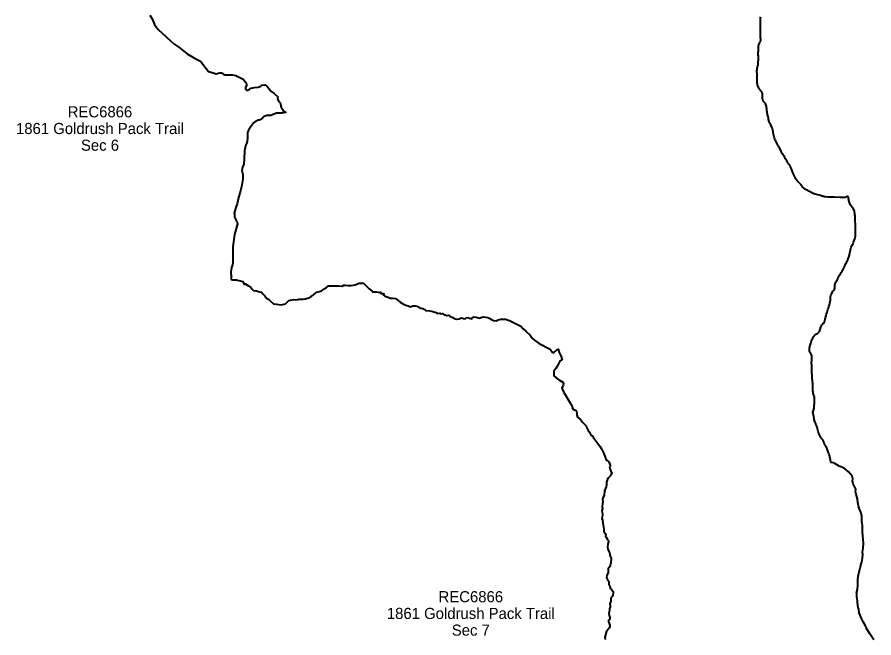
# Model space of a CAD drawing. Extents: x 322505 to 642419, y 5806860 to 5919753.
# Drawn here: x 603068 to 610765, y 5865060 to 5870637 of the extents above; entities that cross this region are included whole.
import ezdxf
from ezdxf.enums import TextEntityAlignment as Align

# ---------------------------------------------------------------- set-up
doc = ezdxf.new("R2010")
doc.units = 0
doc.header["$LTSCALE"] = 140
doc.layers.add('4', color=7, linetype='Continuous', lineweight=40)
doc.layers.add('5', color=7, linetype='Continuous', lineweight=40)

msp = doc.modelspace()

# ---------------------------------------------------------------- linework, layer by layer
at = {"layer": '4'}
for points in [[(604262, 5870655), (604282, 5870623), (604303, 5870571), (604308, 5870561), (604336, 5870526), (604408, 5870459), (604475, 5870399), (604522, 5870368), (604597, 5870309), (604663, 5870268), (604715, 5870243), (604788, 5870148), (604822, 5870141), (604858, 5870128), (604868, 5870130), (604876, 5870135), (604889, 5870138), (604904, 5870138), (604914, 5870132), (604926, 5870121), (604934, 5870119), (605004, 5870119), (605033, 5870114), (605099, 5870079), (605125, 5870047), (605130, 5870028), (605129, 5870019), (605121, 5870005), (605120, 5869989), (605128, 5869981), (605140, 5869981), (605152, 5869986), (605171, 5869998), (605185, 5870003), (605200, 5870005), (605235, 5870007), (605258, 5870017), (605268, 5870025), (605297, 5870030), (605312, 5870016)], [(605312, 5870016), (605317, 5870011), (605332, 5869993), (605347, 5869973), (605377, 5869951), (605413, 5869918), (605409, 5869912), (605409, 5869905), (605411, 5869896), (605418, 5869882), (605428, 5869871), (605436, 5869858), (605437, 5869837), (605440, 5869830), (605451, 5869811), (605464, 5869794), (605482, 5869781), (605480, 5869781), (605475, 5869781), (605471, 5869781), (605466, 5869780), (605460, 5869779), (605453, 5869777), (605445, 5869776), (605437, 5869775), (605433, 5869775), (605429, 5869775), (605425, 5869775), (605422, 5869775), (605419, 5869775), (605417, 5869775), (605413, 5869775), (605409, 5869775), (605405, 5869774), (605400, 5869774), (605396, 5869773), (605392, 5869772), (605388, 5869771), (605385, 5869769), (605383, 5869769), (605379, 5869767), (605375, 5869765), (605370, 5869763), (605364, 5869760), (605359, 5869758), (605355, 5869756), (605350, 5869755), (605346, 5869755), (605341, 5869754), (605336, 5869754), (605331, 5869754), (605327, 5869754), (605322, 5869754), (605318, 5869754), (605315, 5869754), (605313, 5869754), (605298, 5869748), (605281, 5869741), (605279, 5869739), (605278, 5869738), (605275, 5869735), (605273, 5869732), (605270, 5869728), (605266, 5869726), (605265, 5869724), (605263, 5869722), (605261, 5869721), (605260, 5869719), (605259, 5869718), (605257, 5869717), (605254, 5869716), (605251, 5869715), (605249, 5869714), (605248, 5869714), (605244, 5869713), (605237, 5869711), (605229, 5869708), (605223, 5869705), (605217, 5869702), (605212, 5869699)], [(605212, 5869699), (605207, 5869696), (605201, 5869692), (605195, 5869688), (605189, 5869684), (605185, 5869680), (605182, 5869677), (605179, 5869673), (605176, 5869669), (605173, 5869664), (605170, 5869659), (605164, 5869649), (605158, 5869640), (605152, 5869631), (605147, 5869622), (605143, 5869613), (605141, 5869607), (605139, 5869601), (605139, 5869594), (605138, 5869587), (605138, 5869580), (605138, 5869573), (605139, 5869568), (605139, 5869566), (605139, 5869558), (605139, 5869549), (605138, 5869540), (605136, 5869530), (605134, 5869520), (605131, 5869511), (605128, 5869503), (605125, 5869497), (605122, 5869490), (605120, 5869481), (605117, 5869471), (605116, 5869460), (605113, 5869451), (605112, 5869439), (605111, 5869427), (605110, 5869415), (605110, 5869402), (605109, 5869390), (605109, 5869378), (605109, 5869365), (605109, 5869363), (605104, 5869316), (605093, 5869289), (605087, 5869256), (605089, 5869248), (605095, 5869224), (605097, 5869208), (605095, 5869188), (605095, 5869186), (605087, 5869127), (605072, 5869064), (605058, 5869016), (605044, 5868960), (605034, 5868928), (605018, 5868875), (605020, 5868867), (605022, 5868845), (605025, 5868833), (605026, 5868831), (605034, 5868816), (605043, 5868804), (605047, 5868779), (605022, 5868685), (605008, 5868599), (605005, 5868572), (605007, 5868485), (605007, 5868434), (605002, 5868411), (604995, 5868389), (604987, 5868347), (604992, 5868308), (604993, 5868306), (604992, 5868296), (604989, 5868279)], [(604989, 5868279), (605003, 5868278.5), (605039.1, 5868276), (605049, 5868274), (605084.4, 5868265.8), (605096.6, 5868262.2), (605107.1, 5868235.6), (605118.5, 5868239.9), (605147.2, 5868223.6), (605167.9, 5868209.1), (605180.6, 5868194.1), (605192.8, 5868180.3), (605219, 5868179), (605245.7, 5868169.6), (605263.3, 5868165.1), (605280.2, 5868147.7), (605293.5, 5868133.7), (605309.1, 5868112.6), (605325.4, 5868104.6), (605342.7, 5868088), (605371.4, 5868061), (605399.5, 5868058.7), (605439.4, 5868054), (605480.2, 5868062.2), (605493.4, 5868076.3), (605509.5, 5868090), (605525.2, 5868094.7), (605550.5, 5868101.5), (605568, 5868098.1), (605589, 5868099.4), (605600.7, 5868104), (605617.8, 5868104.4), (605638.1, 5868102.5), (605658.3, 5868105.1), (605688.4, 5868114.5), (605709.2, 5868127.3), (605731.3, 5868141.2), (605752.4, 5868160.4), (605758.9, 5868166.7), (605799.3, 5868176.7), (605832.9, 5868198.3), (605844.7, 5868205.3), (605864.4, 5868223.8), (605928, 5868221.8), (605959.7, 5868223), (605990, 5868219.3), (606003.8, 5868229.1), (606019.9, 5868229.7), (606041.4, 5868225.1), (606070, 5868225.4), (606104.5, 5868232), (606138.5, 5868248.6), (606178.7, 5868248.5), (606207.2, 5868219.7), (606231.6, 5868195.8), (606259.4, 5868174.2), (606260.9, 5868170.3), (606295.7, 5868170.7), (606312.9, 5868167.1), (606323.3, 5868163.2), (606328.7, 5868166.9), (606332.9, 5868166.9), (606336.5, 5868156.1), (606341.8, 5868153.7), (606344.6, 5868152.7), (606352.7, 5868155.1), (606361.2, 5868153.1), (606363.5, 5868149)], [(606363.5, 5868149), (606362.7, 5868145.8), (606360.7, 5868144.9), (606360, 5868138.6), (606367.4, 5868133.5), (606371.9, 5868132.8), (606374.8, 5868129.3), (606389.7, 5868124.2), (606402.7, 5868121.2), (606419.2, 5868113.1), (606444.6, 5868111.2), (606466.7, 5868108.8), (606488.5, 5868094.1), (606510.5, 5868077.9), (606539.3, 5868059.1), (606559.2, 5868048.6), (606582.7, 5868042.1), (606602.9, 5868035.9), (606624.7, 5868042.7), (606647.3, 5868044.8), (606662.6, 5868041), (606696, 5868022.8), (606714.4, 5868019), (606730.3, 5868010.5), (606739, 5868001.6), (606777.1, 5867998.1), (606793.1, 5867996.4), (606821.5, 5867986.9), (606834, 5867984.3), (606846.5, 5867974.7), (606867.1, 5867977.5), (606874.7, 5867973), (606890.7, 5867974.7), (606910.1, 5867962.2), (606926.1, 5867956.8), (606944.9, 5867959), (606958.3, 5867947.1), (606984.1, 5867939.8), (606995.3, 5867928.7), (607016.9, 5867925), (607040.1, 5867928.2), (607058.5, 5867935.4), (607077.5, 5867930.9), (607092.9, 5867926.6), (607103, 5867936), (607116.8, 5867939.6), (607133, 5867931.8), (607153.9, 5867927.6), (607160.8, 5867938.8), (607170.8, 5867944.6), (607192, 5867941.5), (607221.1, 5867932.8), (607244.5, 5867941.8), (607259.8, 5867944.4), (607295.8, 5867940.2), (607313.7, 5867929.7), (607330.2, 5867921.5), (607347.2, 5867911.9), (607373, 5867909), (607390.7, 5867916.8), (607413.3, 5867924.3), (607430.5, 5867924.1), (607454.4, 5867923.3), (607473.4, 5867917.6), (607498.6, 5867909.8), (607594.3, 5867861.4), (607614.1, 5867838.3), (607639.3, 5867817.3), (607677.9, 5867778.5), (607696.4, 5867753.8), (607715, 5867735.8), (607738.7, 5867720.3), (607759, 5867705.1)], [(607759, 5867705.1), (607858.1, 5867654.8), (607878, 5867625), (607883.6, 5867623.1), (607890.8, 5867623.4), (607905.3, 5867635.1), (607920.1, 5867652.6), (607928.8, 5867654.2), (607938, 5867625.2), (607956, 5867587.9), (607965.6, 5867558.4), (607943.3, 5867544.9), (607932.2, 5867521.5), (607909.4, 5867480.9), (607890.3, 5867456.3), (607890.9, 5867414.5), (607924.9, 5867383.4), (607936.4, 5867379.3), (607970.2, 5867356.9), (607976.3, 5867343.3), (607972.5, 5867330.5), (607961.9, 5867302.4), (607969.4, 5867291.3), (607976, 5867270.3), (608011.8, 5867211.5), (608040.6, 5867166.1), (608052.7, 5867152), (608055.9, 5867128.6), (608063.6, 5867114.1), (608081, 5867105.1), (608089.6, 5867101.2), (608093.8, 5867093.6), (608096.5, 5867080), (608097.1, 5867063.5), (608103.5, 5867044.4), (608128.3, 5867022.2), (608146.5, 5866999.3), (608179.8, 5866964), (608183.9, 5866953.6), (608195.1, 5866929.5), (608209.8, 5866909.5), (608218.8, 5866889.3), (608226.2, 5866882.7), (608236.3, 5866876.1), (608243.2, 5866864.3), (608250.8, 5866853.1), (608286.8, 5866805.4), (608303.2, 5866781.4), (608319.4, 5866757.9), (608339.1, 5866718), (608361.5, 5866660.1), (608373, 5866653.8), (608383.1, 5866641), (608394.9, 5866612.6), (608395, 5866601), (608391.5, 5866595), (608391.8, 5866581.5), (608402.6, 5866558.8), (608409.8, 5866537.9), (608409.1, 5866532.1), (608395.2, 5866512.2), (608385.4, 5866500.3), (608375, 5866493.8), (608363.5, 5866458), (608363.4, 5866431.1), (608359.1, 5866418), (608346.1, 5866382), (608342.3, 5866338.2), (608333.2, 5866324.5), (608328, 5866307.2), (608329.5, 5866281.9), (608326.1, 5866268.5), (608324.8, 5866237.1), (608325.9, 5866222.3), (608322.2, 5866203.7), (608326.4, 5866168.8), (608327.9, 5866162.9)], [(608327.9, 5866162.9), (608323.9, 5866144.3), (608321.6, 5866131.7), (608325.9, 5866117.6), (608333.2, 5866073.9), (608335.2, 5866054.3), (608339.7, 5866038.4), (608337.9, 5866028.7), (608339, 5866014.7), (608354.2, 5865994.1), (608357.9, 5865985.4), (608353.7, 5865975.2), (608353.8, 5865970.9), (608360.2, 5865963.7), (608370.4, 5865950.4), (608377.7, 5865936.7), (608381, 5865925.9), (608375.1, 5865898.9), (608372.7, 5865876.2), (608379.1, 5865847.2), (608390.4, 5865828.7), (608391.8, 5865812.3), (608393.3, 5865801.6), (608400.9, 5865783.7), (608405.1, 5865774.8), (608406, 5865769.7), (608403.5, 5865737.4), (608399.1, 5865723.5), (608393.2, 5865701.9), (608378.6, 5865680.2), (608378.4, 5865647.6), (608365.5, 5865619.2), (608363.6, 5865602.5), (608366.2, 5865593.1), (608372.5, 5865586.3), (608373.6, 5865577.8), (608383, 5865565.4), (608382.7, 5865548.9), (608385, 5865541.7), (608390.6, 5865532.4), (608392.8, 5865522), (608398.1, 5865501.8), (608409.2, 5865495.8), (608423.3, 5865477.9), (608422.6, 5865464.3), (608420.4, 5865443.1), (608415.8, 5865434.6), (608405.9, 5865422.7), (608402.3, 5865409.1), (608401, 5865391.2), (608395.9, 5865375.6), (608394.3, 5865365.4), (608395.3, 5865344.6), (608396.6, 5865331.3), (608392.1, 5865329), (608390.9, 5865325.2), (608390.8, 5865311.5), (608387.3, 5865293.6), (608384.3, 5865277.8), (608391.4, 5865252.9), (608392.8, 5865242.9), (608391.7, 5865229.1), (608381.4, 5865218.4), (608382.3, 5865204.9), (608388.6, 5865189.3), (608392.4, 5865175.2), (608392.4, 5865159.8), (608385.2, 5865144.2), (608374.4, 5865133.5), (608362.5, 5865120.7), (608355.6, 5865086.6), (608349, 5865066.5), (608351.1, 5865044.6)]]:
    msp.add_lwpolyline(points, dxfattribs=at)
at = {"layer": '5'}
for points in [[(609746, 5870417), (609748, 5870422), (609749, 5870428), (609749, 5870435), (609749, 5870441), (609748, 5870448), (609748, 5870453), (609747, 5870459), (609747, 5870464), (609747, 5870470), (609747, 5870478), (609747, 5870486), (609747, 5870495), (609747, 5870504), (609747, 5870511), (609747, 5870518), (609747, 5870525), (609746, 5870534), (609746, 5870543), (609746, 5870551), (609746, 5870560), (609746, 5870568), (609746, 5870575), (609746, 5870583), (609746, 5870592), (609747, 5870602), (609747, 5870613), (609748, 5870623), (609748, 5870632), (609749, 5870639)], [(609851, 5869643), (609847, 5869652), (609843, 5869661), (609839, 5869670), (609835, 5869678), (609832, 5869684), (609829, 5869691), (609826, 5869699), (609823, 5869709), (609820, 5869719), (609818, 5869730), (609815, 5869741), (609813, 5869750), (609811, 5869760), (609810, 5869769), (609808, 5869779), (609807, 5869789), (609805, 5869797), (609803, 5869815), (609803, 5869817), (609802, 5869825), (609800, 5869834), (609798, 5869843), (609796, 5869851), (609792, 5869860), (609790, 5869864), (609782, 5869871), (609772, 5869883), (609766, 5869907), (609765, 5869939), (609764, 5869951), (609756, 5869970), (609754, 5869971), (609751, 5869975), (609746, 5869980), (609741, 5869987), (609739, 5869990), (609737, 5869992), (609736, 5869995), (609734, 5869997), (609733, 5870000), (609730, 5870005), (609728, 5870010), (609725, 5870015), (609723, 5870021), (609721, 5870025), (609720, 5870031), (609719, 5870038), (609718, 5870045), (609718, 5870054), (609718, 5870063), (609718, 5870073), (609718, 5870080), (609718, 5870087), (609718, 5870093), (609717, 5870100), (609717, 5870106), (609717, 5870112), (609717, 5870118), (609717, 5870124), (609716, 5870129), (609716, 5870135), (609715, 5870141), (609715, 5870148), (609715, 5870156), (609716, 5870164), (609717, 5870176), (609719, 5870185), (609721, 5870193), (609722, 5870197), (609723, 5870201), (609725, 5870209), (609726, 5870217), (609727, 5870226), (609727, 5870234), (609727, 5870242), (609728, 5870248), (609728, 5870254), (609728, 5870261), (609728, 5870269), (609728, 5870277), (609728, 5870287), (609727, 5870296), (609727, 5870303), (609727, 5870310), (609727, 5870316), (609727, 5870323), (609728, 5870332), (609728, 5870341), (609729, 5870351), (609730, 5870359), (609729, 5870366), (609729, 5870371), (609729, 5870376), (609730, 5870382), (609731, 5870389), (609734, 5870396), (609737, 5870403), (609740, 5870408), (609743, 5870413), (609746, 5870417)], [(610316, 5869025), (610308, 5869027), (610301, 5869029), (610296, 5869031), (610291, 5869033), (610286, 5869035), (610274, 5869038), (610262, 5869041), (610250, 5869045), (610238, 5869048), (610228, 5869050), (610224, 5869052), (610218, 5869054), (610212, 5869057), (610205, 5869061), (610198, 5869065), (610188, 5869070), (610180, 5869075), (610172, 5869079), (610166, 5869082), (610158, 5869086), (610152, 5869090), (610146, 5869093), (610139, 5869097), (610134, 5869101), (610130, 5869104), (610126, 5869108), (610123, 5869113), (610120, 5869119), (610116, 5869125), (610111, 5869132), (610105, 5869138), (610101, 5869143), (610096, 5869147), (610092, 5869151), (610088, 5869156), (610084, 5869159), (610081, 5869163), (610078, 5869167), (610077, 5869168), (610075, 5869170), (610073, 5869173), (610068, 5869180), (610062, 5869188), (610058, 5869197), (610052, 5869208), (610047, 5869221), (610043, 5869229), (610040, 5869236), (610038, 5869242), (610035, 5869249), (610032, 5869255), (610028, 5869265), (610024, 5869275), (610019, 5869285), (610015, 5869293), (610015, 5869294), (610011, 5869302), (610009, 5869306), (610006, 5869311), (610002, 5869316), (609997, 5869322), (609993, 5869329), (609985, 5869341), (609980, 5869349), (609979, 5869350), (609974, 5869358), (609969, 5869366), (609964, 5869375), (609958, 5869384), (609952, 5869393), (609946, 5869403), (609941, 5869411), (609937, 5869418), (609934, 5869424), (609931, 5869432), (609927, 5869442), (609922, 5869452), (609917, 5869463), (609912, 5869471), (609907, 5869478), (609903, 5869485), (609902, 5869487), (609899, 5869492), (609895, 5869499), (609891, 5869508), (609887, 5869516), (609884, 5869524), (609881, 5869531), (609879, 5869536), (609877, 5869542), (609874, 5869551), (609871, 5869561), (609868, 5869573), (609865, 5869586), (609862, 5869599), (609860, 5869609), (609860, 5869610), (609857, 5869621), (609854, 5869632), (609851, 5869643)], [(610567, 5868937), (610562, 5868942), (610558, 5868948), (610553, 5868955), (610549, 5868964), (610546, 5868973), (610543, 5868982), (610540, 5868990), (610539, 5868999), (610537, 5869007), (610537, 5869012), (610536.2, 5869017), (610536, 5869018), (610533.2, 5869022), (610529.2, 5869024.5), (610525.2, 5869025.5), (610521.6, 5869024), (610517, 5869021.5), (610511.6, 5869018), (610505.4, 5869017), (610462.1, 5869017.5), (610407.6, 5869018.5), (610355.6, 5869020), (610327, 5869022), (610322, 5869023), (610316, 5869025)], [(610294, 5867863), (610299, 5867872), (610305, 5867880), (610311, 5867887), (610315, 5867892), (610321, 5867900), (610324, 5867911), (610328, 5867923), (610332, 5867938), (610336, 5867955), (610341, 5867973), (610345, 5867987), (610349, 5868000), (610353, 5868011), (610357, 5868023), (610362, 5868037), (610367, 5868052), (610371, 5868067), (610374, 5868081), (610375, 5868093), (610376, 5868102), (610376, 5868113), (610377, 5868124), (610380, 5868136), (610384, 5868149), (610391, 5868163), (610398, 5868174), (610405, 5868183), (610411, 5868192), (610415, 5868202), (610416, 5868209), (610416, 5868216), (610416, 5868224), (610416, 5868231), (610417, 5868238), (610418, 5868244), (610421, 5868250), (610425, 5868257), (610429, 5868264), (610434, 5868272), (610438, 5868280), (610442, 5868287), (610445, 5868294), (610448, 5868300), (610451, 5868306), (610457, 5868318), (610465, 5868331), (610472, 5868343), (610480, 5868355), (610487, 5868367), (610492, 5868377), (610496, 5868387), (610501, 5868398), (610506, 5868410), (610513, 5868423), (610518, 5868434), (610523, 5868443), (610528, 5868450), (610532, 5868458), (610535, 5868466), (610538, 5868474), (610541, 5868482), (610543, 5868490), (610545, 5868498), (610547, 5868506), (610549, 5868520), (610551, 5868533), (610554, 5868546), (610557, 5868558), (610562, 5868570), (610565, 5868579), (610570, 5868587), (610574, 5868595), (610578, 5868604), (610583, 5868616), (610588, 5868632), (610593, 5868645), (610596, 5868657), (610599, 5868668), (610600, 5868679), (610601, 5868693), (610601, 5868708), (610601, 5868724), (610600, 5868740), (610599, 5868758), (610599, 5868771), (610599, 5868783), (610598, 5868795), (610598, 5868808), (610597, 5868823), (610597, 5868838), (610596, 5868851), (610595, 5868862), (610595, 5868873), (610592, 5868885), (610590, 5868894), (610586, 5868903), (610582, 5868912), (610577, 5868921), (610571, 5868930), (610567, 5868937)], [(610271, 5866898), (610268, 5866906), (610266, 5866915), (610262, 5866927), (610260, 5866937), (610258, 5866945), (610255, 5866953), (610253, 5866962), (610250, 5866968), (610248, 5866975), (610245, 5866981), (610243, 5866986), (610241, 5866991), (610238, 5866997), (610235, 5867004), (610233, 5867012), (610230, 5867021), (610228, 5867031), (610226, 5867042), (610225, 5867051), (610224, 5867058), (610223, 5867066), (610221, 5867074), (610220, 5867077), (610218, 5867083), (610217.1, 5867085.5), (610224, 5867104.5), (610227.8, 5867125.5), (610229.9, 5867146), (610230.6, 5867166.5), (610231.6, 5867187), (610231.9, 5867204.5), (610231, 5867226), (610226, 5867239), (610225.3, 5867241.5), (610223, 5867250), (610221, 5867260), (610219, 5867270), (610218, 5867280), (610218, 5867294), (610217, 5867308), (610217, 5867322), (610217, 5867336), (610216, 5867348), (610215, 5867361), (610214, 5867375), (610212, 5867389), (610211, 5867406), (610210, 5867424), (610209, 5867440), (610209, 5867453), (610208, 5867466), (610208, 5867477), (610208, 5867489), (610207, 5867501), (610207, 5867513), (610206, 5867526), (610206, 5867538), (610207, 5867550), (610208, 5867561), (610209, 5867572), (610209, 5867583), (610207, 5867596), (610203, 5867608), (610199, 5867615), (610196, 5867621), (610193, 5867626), (610190, 5867631), (610188, 5867637), (610187, 5867642), (610187, 5867649), (610187, 5867655), (610188, 5867661), (610188, 5867666), (610189, 5867673), (610190, 5867680), (610192, 5867686), (610192, 5867687), (610195, 5867696), (610198, 5867706), (610202, 5867718), (610205, 5867728), (610208, 5867737), (610212, 5867745), (610216, 5867754), (610220, 5867762), (610226, 5867770), (610232, 5867778), (610239, 5867784), (610246, 5867790), (610252, 5867793), (610258, 5867796), (610265, 5867800), (610271, 5867806), (610276, 5867813), (610281, 5867822), (610283, 5867831), (610285, 5867839), (610287, 5867847), (610289, 5867855), (610294, 5867863)], [(610765.2, 5865042), (610753.5, 5865061), (610747, 5865069.5), (610730.1, 5865096), (610696.2, 5865151), (610692.2, 5865162), (610692.2, 5865163.5), (610689.6, 5865167), (610670, 5865203.5), (610666.1, 5865210), (610653, 5865235), (610641.1, 5865264), (610634.4, 5865286.5), (610628.8, 5865318), (610623.5, 5865331.5), (610621.9, 5865355.5), (610618.9, 5865382), (610618.8, 5865392.5), (610613.1, 5865430), (610611.3, 5865459), (610610, 5865461.5), (610617.1, 5865493.5), (610620.2, 5865537.5), (610622.5, 5865555.5), (610620.8, 5865582), (610625.4, 5865613.5), (610634.8, 5865665.5), (610641.9, 5865691), (610655.2, 5865733), (610656.4, 5865741.5), (610662.2, 5865776), (610666.7, 5865810), (610663.8, 5865831.5), (610669.6, 5865867), (610672.8, 5865907.5), (610669.6, 5865949), (610665.3, 5865975.5), (610663.4, 5866020), (610662.6, 5866069), (610656.9, 5866105.5), (610656.4, 5866137.5), (610656.1, 5866160), (610649.2, 5866189), (610633.4, 5866226.5), (610628, 5866248), (610621.2, 5866277), (610618.2, 5866308.5), (610604.8, 5866349), (610600.6, 5866375), (610602.8, 5866395.5), (610579.2, 5866445.5), (610573.7, 5866471), (610577.2, 5866488.5), (610570.5, 5866512.5), (610555, 5866531), (610536.8, 5866553.5), (610516.2, 5866570), (610498.2, 5866584.5), (610468.9, 5866595.5), (610454.8, 5866603), (610415.1, 5866627.5), (610399.8, 5866632.5), (610380.3, 5866635.5), (610379, 5866641), (610377, 5866653), (610375, 5866663), (610373, 5866673), (610373, 5866675), (610371, 5866682), (610369, 5866693), (610365, 5866704), (610361, 5866716), (610356, 5866731), (610352, 5866741), (610349, 5866750), (610346, 5866759), (610343, 5866766), (610339, 5866774), (610336, 5866780), (610332, 5866786), (610328, 5866793), (610325, 5866799), (610322, 5866804), (610320, 5866809), (610318, 5866815), (610316, 5866820), (610313, 5866827), (610309, 5866833), (610306, 5866840), (610302, 5866845), (610299, 5866850), (610296, 5866854), (610293, 5866859), (610290, 5866864), (610286, 5866868), (610283, 5866873), (610281, 5866878), (610278, 5866882), (610275, 5866886), (610273, 5866892), (610271, 5866898)]]:
    msp.add_lwpolyline(points, dxfattribs=at)

# ---------------------------------------------------------------- texts
at = {"layer": '4'}
for s, p in [('REC6866', (603812.7, 5869736.9)), ('1861 Goldrush Pack Trail', (603812.7, 5869586.9)), ('Sec 6', (603812.7, 5869436.9)), ('REC6866', (607144.3, 5865380)), ('1861 Goldrush Pack Trail', (607144.3, 5865230)), ('Sec 7', (607144.3, 5865080))]:
    msp.add_text(s, height=100, dxfattribs=at).set_placement(p, align=Align.CENTER)

doc.saveas('drawing.dxf')
